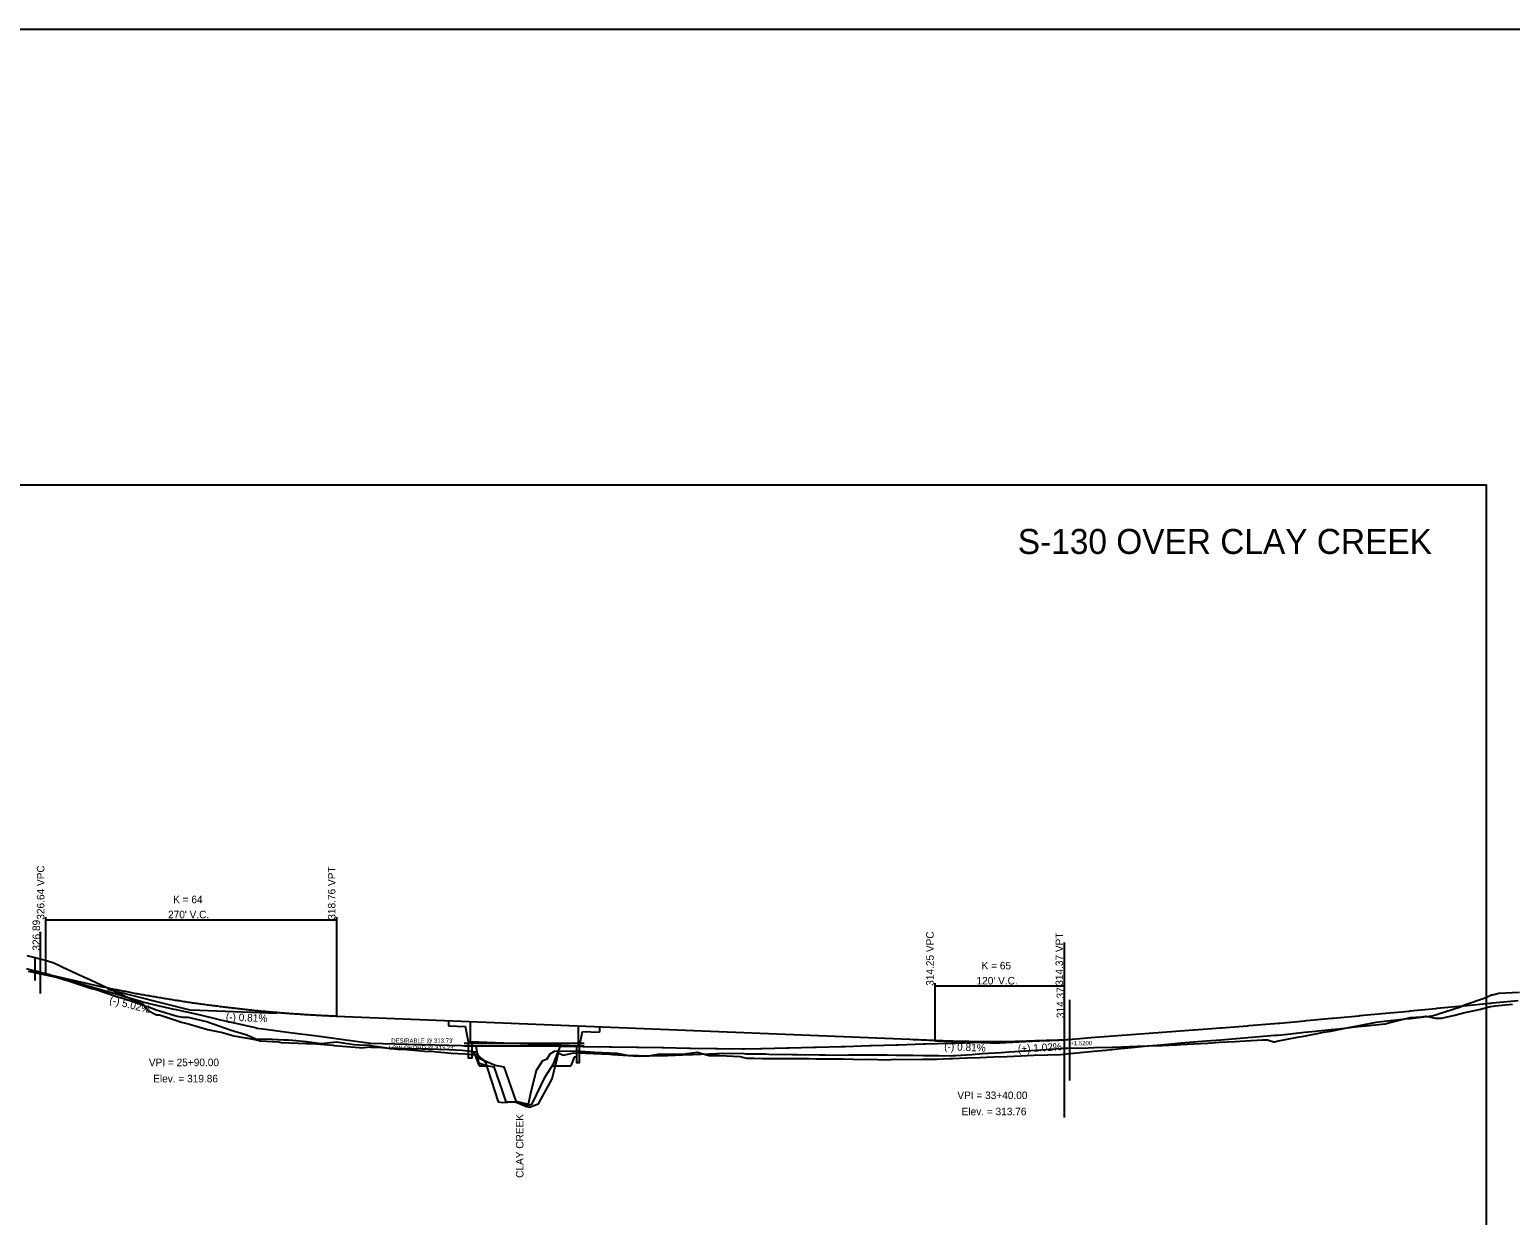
# Model space of a CAD drawing. Extents: x 2230305 to 2233905, y 1078764 to 1080964.
# Drawn here: x 2231649 to 2233023, y 1079864 to 1080964 of the extents above; entities that cross this region are included whole.
import ezdxf

# ---------------------------------------------------------------- set-up
doc = ezdxf.new("R2010")
doc.units = 0
for name, color, linetype in [('BR_CONCRETE', 7, 'Continuous'), ('BR_EXIST_GROUND_LT', 7, 'Continuous'), ('BR_EXIST_GROUND_RT', 7, 'Continuous'), ('BR_USER NOTES', 7, 'Continuous'), ('RD_DDB_GradeTX', 7, 'Continuous'), ('RD_DDB_Profile_EX', 7, 'Continuous'), ('RD_DDB_Profile_Lbl', 7, 'Continuous'), ('RD_DDB_Profile_PR', 7, 'Continuous'), ('RD_DDB_StripGrade', 7, 'Continuous'), ('RD_DDB_VCLbl', 7, 'Continuous'), ('RD_SHT_IplotShp', 7, 'Continuous'), ('RD_SHT_ShtClip', 7, 'Continuous'), ('RD_SHT_TX', 7, 'Continuous')]:
    doc.layers.add(name, color=color, linetype=linetype)

msp = doc.modelspace()

# ---------------------------------------------------------------- linework, layer by layer
at = {"layer": 'BR_CONCRETE'}
for p, q in [((2232038.2, 1080044.4), (2232038.2, 1080039.4)), ((2232038.2, 1080039.4), (2232053.9, 1080038.8)), ((2232056.7, 1080024.7), (2232053.9, 1080038.8)), ((2232058.2, 1080043.6), (2232058.2, 1080025.1)), ((2232158.2, 1080039.5), (2232158.2, 1080021)), ((2232178.2, 1080038.7), (2232178.2, 1080033.7)), ((2232058.2, 1080025.1), (2232158.2, 1080021)), ((2232058.2, 1080025.1), (2232058.2, 1080024.7)), ((2232159.7, 1080020.6), (2232162.4, 1080034.4)), ((2232162.4, 1080034.4), (2232178.2, 1080033.7)), ((2232059.7, 1080014.7), (2232061.7, 1080014.7)), ((2232061.7, 1080014.7), (2232066.6, 1080002.3)), ((2232154.7, 1080010.6), (2232151.4, 1080002.3)), ((2232156.7, 1080010.6), (2232154.7, 1080010.6)), ((2232158.2, 1080021), (2232158.2, 1080020.6)), ((2232066.6, 1080002.3), (2232074.8, 1080002.3)), ((2232134.2, 1080002.3), (2232151.4, 1080002.3))]:
    msp.add_line(p, q, dxfattribs=at)
for points in [[(2232056.7, 1080024.7), (2232059.7, 1080024.7), (2232059.7, 1080009.7), (2232056.7, 1080009.7)], [(2232159.7, 1080020.6), (2232156.7, 1080020.6), (2232156.7, 1080005.6), (2232159.7, 1080005.6)]]:
    msp.add_lwpolyline(points, close=True, dxfattribs=at)
at = {"layer": 'BR_EXIST_GROUND_LT'}
msp.add_lwpolyline([(2231647, 1080104.8), (2231665, 1080100.1), (2231672, 1080097.9), (2231677.9, 1080095.1), (2231680.4, 1080094), (2231697.7, 1080085.9), (2231705.3, 1080082.4), (2231721.7, 1080074.7), (2231730.2, 1080070.8), (2231745.4, 1080063.7), (2231755.2, 1080059.2), (2231758.7, 1080054.1), (2231767.3, 1080049.8), (2231768.6, 1080049.9), (2231769.9, 1080049.6), (2231790.3, 1080042.8), (2231797.9, 1080041.2), (2231814.6, 1080036), (2231828.5, 1080033.3), (2231839, 1080030.3), (2231858.8, 1080026.9), (2231863.4, 1080025.7), (2231864.1, 1080025.5), (2231880.5, 1080024.7), (2231882.8, 1080024.1), (2231906.4, 1080023.3), (2231906.8, 1080023.3), (2231911.7, 1080023.2), (2231930.9, 1080021.5), (2231931.9, 1080021.4), (2231955.1, 1080019.3), (2231957.2, 1080019), (2231965, 1080020.1), (2231965.7, 1080020), (2231966.3, 1080019.9), (2231973.5, 1080019.7), (2231990.8, 1080017.9), (2231999.3, 1080017.7), (2232015.7, 1080016), (2232024.9, 1080015.8), (2232040.6, 1080014.3), (2232053.5, 1080013.6), (2232064.4, 1080012.6), (2232066.2, 1080011.1), (2232070.3, 1080008.1), (2232072.3, 1080005.4), (2232074.7, 1079998.7), (2232084.2, 1079969.1), (2232088.3, 1079968.3), (2232097.9, 1079969.1), (2232101.7, 1079969.2), (2232112.3, 1079966.8), (2232114.1, 1079975.8), (2232119.8, 1079998.3), (2232125.7, 1080007.3), (2232129.5, 1080008.9), (2232132.5, 1080013.6), (2232136.5, 1080016.1), (2232156.6, 1080016.3), (2232173.8, 1080015), (2232194.1, 1080014.3), (2232205, 1080012.1), (2232214.4, 1080011.9), (2232223.3, 1080011.8), (2232234.5, 1080013.5), (2232254.7, 1080013.4), (2232268.6, 1080015.2), (2232279.9, 1080012.1), (2232289.4, 1080012), (2232289.8, 1080012), (2232308.3, 1080011.2), (2232314.5, 1080009.4), (2232321.3, 1080009.4), (2232329.4, 1080009.3), (2232344.2, 1080009.2), (2232354.3, 1080009.1), (2232372.4, 1080009.1), (2232379.2, 1080009), (2232399.8, 1080009), (2232404.2, 1080008.9), (2232422.1, 1080008.3), (2232428.1, 1080008.5), (2232444.5, 1080008.1), (2232453.1, 1080008.5), (2232467.6, 1080008.2), (2232478.1, 1080008.7), (2232490.9, 1080008.6), (2232503.1, 1080009.2), (2232504.5, 1080009.2), (2232505.9, 1080009.3), (2232518.7, 1080009.8), (2232530.9, 1080010.2), (2232543.8, 1080010.7), (2232555.9, 1080011.2), (2232568.9, 1080011.7), (2232580.9, 1080012.2), (2232594, 1080012.6), (2232605.9, 1080013.1), (2232608.8, 1080013.4), (2232611.8, 1080013.7), (2232624.1, 1080014.7), (2232636.8, 1080016), (2232647.9, 1080017), (2232661.9, 1080018.4), (2232671.7, 1080019.3), (2232686.9, 1080020.9), (2232695.5, 1080021.6), (2232712, 1080023.3), (2232717.3, 1080023.7), (2232729.6, 1080024.7), (2232737, 1080025.2), (2232754.6, 1080026.7), (2232761.8, 1080027.2), (2232779.6, 1080028.7), (2232786.6, 1080029.2), (2232804.6, 1080030.8), (2232805.4, 1080030.8), (2232807, 1080031), (2232813.9, 1080031.6), (2232832, 1080033.6), (2232838.9, 1080034.2), (2232857, 1080036.2), (2232864, 1080036.8), (2232882, 1080038.8), (2232889.1, 1080039.4), (2232906.9, 1080041.3), (2232910.4, 1080042.2), (2232916.6, 1080043.8), (2232930.2, 1080047.2), (2232940.4, 1080047.9), (2232942.6, 1080048.1), (2232944.8, 1080048.5), (2232953.8, 1080046.8), (2232954.8, 1080046.8), (2232959.2, 1080046.8), (2232971.6, 1080049.4), (2232979.8, 1080051.5), (2232994.1, 1080054.8), (2233004.8, 1080057.6), (2233007.1, 1080057.8), (2233009, 1080058.2), (2233025.2, 1080059.7)], dxfattribs=at)
at = {"layer": 'BR_EXIST_GROUND_RT'}
msp.add_lwpolyline([(2231648, 1080090.3), (2231651.1, 1080089.7), (2231673, 1080085.1), (2231674.4, 1080084.7), (2231682.1, 1080082.2), (2231686.4, 1080081.1), (2231707, 1080074.2), (2231711.2, 1080073.2), (2231731.9, 1080066.1), (2231736.1, 1080065.3), (2231756.9, 1080058), (2231757.5, 1080057.8), (2231761.5, 1080056.5), (2231766.8, 1080054.4), (2231786.4, 1080048.6), (2231791.5, 1080047.6), (2231796.7, 1080047.6), (2231797.8, 1080047.3), (2231799.1, 1080047), (2231814.9, 1080043.2), (2231815.5, 1080043.1), (2231836.4, 1080035.5), (2231850.9, 1080031.3), (2231859.8, 1080027.3), (2231860.5, 1080027.3), (2231868.9, 1080027.6), (2231885.2, 1080026.5), (2231889.7, 1080026.6), (2231906.4, 1080025), (2231910.2, 1080024.4), (2231910.9, 1080024.3), (2231920, 1080023.2), (2231934.2, 1080024.6), (2231950.5, 1080022.1), (2231955.5, 1080021.8), (2231965.1, 1080021.5), (2231965.7, 1080021.4), (2231980.9, 1080019.1), (2231991.2, 1080018.9), (2232002.8, 1080018.6), (2232013.4, 1080018.2), (2232018.9, 1080018.1), (2232038.4, 1080017.6), (2232050.6, 1080016.9), (2232063.8, 1080015.3), (2232067, 1080009.2), (2232081.3, 1080003), (2232089.3, 1080001.6), (2232097.9, 1079976.7), (2232100.7, 1079968.6), (2232110.4, 1079964.6), (2232113.3, 1079964.1), (2232119.8, 1079966.7), (2232121.7, 1079967.1), (2232134.1, 1079990.5), (2232139.3, 1080010.4), (2232140.1, 1080014.3), (2232140.7, 1080014.1), (2232144.3, 1080012.2), (2232154.4, 1080014.4), (2232164.7, 1080014.2), (2232179.9, 1080013.6), (2232184.9, 1080013.5), (2232190.4, 1080013.1), (2232209.6, 1080011.6), (2232215.4, 1080011.5), (2232233.4, 1080012.1), (2232237.1, 1080012.1), (2232241.3, 1080012.1), (2232262.1, 1080012.9), (2232264.6, 1080012.9), (2232287.1, 1080013.9), (2232287.6, 1080013.9), (2232292.6, 1080014.1), (2232312.1, 1080013.8), (2232313.8, 1080013.7), (2232332, 1080013.5), (2232335.2, 1080013.4), (2232356.9, 1080013.1), (2232361.4, 1080013), (2232381.8, 1080012.7), (2232387.7, 1080012.5), (2232406.7, 1080012.2), (2232409.8, 1080012.7), (2232425, 1080012.6), (2232428.7, 1080012.6), (2232445, 1080012.5), (2232453.7, 1080012.3), (2232468.8, 1080012.3), (2232478.8, 1080012.1), (2232492.7, 1080012), (2232503.9, 1080011.8), (2232506.4, 1080011.9), (2232508.4, 1080012.1), (2232523.6, 1080013.1), (2232533.2, 1080013.8), (2232550.9, 1080014.9), (2232558.1, 1080015.4), (2232578.3, 1080016.8), (2232583, 1080017.1), (2232605.8, 1080018.6), (2232607.8, 1080018.8), (2232611.8, 1080018.9), (2232612.3, 1080018.9), (2232631.5, 1080019.2), (2232637.4, 1080019.5), (2232654, 1080019.8), (2232662.4, 1080020.2), (2232676.9, 1080020.6), (2232687.5, 1080021), (2232700.1, 1080021.3), (2232712.6, 1080021.9), (2232713.6, 1080022), (2232717.4, 1080022.1), (2232729.2, 1080022.9), (2232742.6, 1080023.6), (2232753.4, 1080024.3), (2232767.9, 1080025.1), (2232777.5, 1080025.7), (2232793.2, 1080026.5), (2232797.8, 1080026.5), (2232803.7, 1080024.7), (2232804.5, 1080024.8), (2232806.5, 1080025.2), (2232825.7, 1080029.1), (2232831.5, 1080030), (2232850.1, 1080033.8), (2232856.5, 1080034.7), (2232874.4, 1080038.4), (2232881.4, 1080039.4), (2232898.5, 1080042.9), (2232906.4, 1080044), (2232925.8, 1080046.1), (2232930.5, 1080046.3), (2232950.4, 1080048.7), (2232954.8, 1080050), (2232955.5, 1080050.4), (2232976.9, 1080057.2), (2232980.6, 1080058.9), (2232999.7, 1080065.4), (2233005.6, 1080068.2), (2233006.6, 1080068.2), (2233012.4, 1080069.7), (2233031.5, 1080070.8)], dxfattribs=at)
at = {"layer": 'BR_USER NOTES'}
for p, q in [((2231659.2, 1080126.7), (2231659.2, 1080069.6)), ((2232609.2, 1080117), (2232609.2, 1079954.6)), ((2231654.2, 1080103.6), (2231654.2, 1080081.5)), ((2231659.2, 1080089.3), (2231654.2, 1080090.7)), ((2232614.2, 1080063.7), (2232614.2, 1079988.8)), ((2232609.2, 1080026.7), (2232614.2, 1080027.1)), ((2232052.7, 1080023.5), (2232164, 1080023.5)), ((2232052.7, 1080021), (2232164, 1080021))]:
    msp.add_line(p, q, dxfattribs=at)
at = {"layer": 'RD_DDB_GradeTX'}
for p, q in [((2231721.6, 1080073.6), (2231799.2, 1080054.1)), ((2231879.1, 1080050.9), (2231799.2, 1080054.1)), ((2232469.2, 1080026.9), (2232549.2, 1080023.6)), ((2232489.2, 1080025.5), (2232549.2, 1080023.6)), ((2232609.2, 1080026.7), (2232549.2, 1080023.6))]:
    msp.add_line(p, q, dxfattribs=at)
at = {"layer": 'RD_DDB_Profile_EX'}
msp.add_lwpolyline([(2231646.7, 1080092.7), (2231668.3, 1080086.7), (2231671.7, 1080085.8), (2231679.3, 1080083.6), (2231680.5, 1080083.3), (2231702.4, 1080076.9), (2231705.5, 1080076), (2231727.6, 1080069.7), (2231730.4, 1080068.8), (2231752.8, 1080062.4), (2231755.4, 1080061.6), (2231759.8, 1080060.6), (2231760.3, 1080060.4), (2231783.4, 1080055.1), (2231785.3, 1080054.7), (2231808.9, 1080049.3), (2231810.2, 1080049), (2231834.3, 1080043.4), (2231835.2, 1080043.2), (2231859.8, 1080037.6), (2231860.1, 1080037.5), (2231865.8, 1080036.7), (2231866.1, 1080036.7), (2231891, 1080033.4), (2231915.9, 1080030.2), (2231940.8, 1080026.9), (2231965.7, 1080023.6), (2231988.5, 1080023), (2232012.8, 1080022.3), (2232013.5, 1080022.3), (2232037.5, 1080021.6), (2232038.5, 1080021.6), (2232062.1, 1080020.9), (2232063.5, 1080020.9), (2232065.9, 1080005.1), (2232073.3, 1080002.6), (2232080.2, 1080001.4), (2232087.9, 1079979.1), (2232091.4, 1079969.1), (2232100, 1079969.1), (2232104.1, 1079967.4), (2232112.5, 1079965.9), (2232115.6, 1079967.2), (2232127.8, 1079992.3), (2232135.4, 1080004.2), (2232141.8, 1080020.2), (2232142.2, 1080020.7), (2232162.7, 1080020.4), (2232164.2, 1080020.4), (2232187.5, 1080020.1), (2232189.2, 1080020), (2232212.4, 1080019.7), (2232214.2, 1080019.7), (2232236.1, 1080019.3), (2232237.7, 1080019.3), (2232260.9, 1080018.9), (2232262.7, 1080018.9), (2232285.8, 1080018.5), (2232287.7, 1080018.5), (2232310.7, 1080018.1), (2232312.7, 1080018.1), (2232327.7, 1080018.5), (2232329.1, 1080018.5), (2232352, 1080019.1), (2232354.1, 1080019.2), (2232377.1, 1080019.8), (2232379.1, 1080019.8), (2232402.2, 1080020.4), (2232404.1, 1080020.5), (2232405.9, 1080020.5), (2232428.8, 1080021.2), (2232430.6, 1080021.3), (2232453.8, 1080022), (2232455.4, 1080022), (2232478.8, 1080022.7), (2232480.3, 1080022.8), (2232504, 1080023.5), (2232507.3, 1080023.6), (2232508.6, 1080023.6), (2232532.3, 1080024.3), (2232533.2, 1080024.4), (2232557.3, 1080025.1), (2232557.9, 1080025.1), (2232582.5, 1080025.8), (2232592.6, 1080026.1), (2232607.4, 1080026.5), (2232613, 1080027), (2232638, 1080028.9), (2232663, 1080030.8), (2232688, 1080032.7), (2232712.9, 1080034.6), (2232729.2, 1080035.8), (2232729.8, 1080035.9), (2232754.2, 1080037.7), (2232755.2, 1080037.8), (2232779.2, 1080039.6), (2232780.6, 1080039.8), (2232804.2, 1080041.6), (2232804.5, 1080041.6), (2232807.6, 1080041.9), (2232809.4, 1080042.1), (2232832.6, 1080044.2), (2232834.1, 1080044.4), (2232857.6, 1080046.6), (2232858.8, 1080046.7), (2232882.5, 1080048.9), (2232883.5, 1080049), (2232907.5, 1080051.2), (2232929.2, 1080053.3), (2232930, 1080053.4), (2232954, 1080055.7), (2232955, 1080055.8), (2232978.8, 1080058.1), (2232979.9, 1080058.2), (2233003.7, 1080060.5), (2233004.9, 1080060.6), (2233006.6, 1080060.8), (2233030.3, 1080063)], dxfattribs=at)
at = {"layer": 'RD_DDB_Profile_PR'}
for p, q in [((2231659.2, 1080089.3), (2231664.2, 1080088)), ((2231934.2, 1080048.6), (2232489.2, 1080026.1))]:
    msp.add_line(p, q, dxfattribs=at)
for points in [[(2231664.2, 1080088), (2231669.6, 1080086.7), (2231675, 1080085.4), (2231680.4, 1080084.1), (2231685.8, 1080082.8), (2231691.2, 1080081.5), (2231696.6, 1080080.3), (2231702, 1080079.1), (2231707.4, 1080077.9), (2231712.8, 1080076.7), (2231718.2, 1080075.6), (2231723.6, 1080074.5), (2231729, 1080073.4), (2231734.4, 1080072.3), (2231739.8, 1080071.3), (2231745.2, 1080070.2), (2231750.6, 1080069.2), (2231756, 1080068.3), (2231761.4, 1080067.3), (2231766.8, 1080066.4), (2231772.2, 1080065.5), (2231777.6, 1080064.6), (2231783, 1080063.7), (2231788.4, 1080062.9), (2231793.8, 1080062), (2231799.2, 1080061.2), (2231804.6, 1080060.5), (2231810, 1080059.7), (2231815.4, 1080059), (2231820.8, 1080058.3), (2231826.2, 1080057.6), (2231831.6, 1080056.9), (2231837, 1080056.3), (2231842.4, 1080055.7), (2231847.8, 1080055.1), (2231853.2, 1080054.5), (2231858.6, 1080053.9), (2231864, 1080053.4), (2231869.4, 1080052.9), (2231874.8, 1080052.4), (2231880.2, 1080052), (2231885.6, 1080051.5), (2231891, 1080051.1), (2231896.4, 1080050.7), (2231901.8, 1080050.4), (2231907.2, 1080050), (2231912.6, 1080049.7), (2231918, 1080049.4), (2231923.4, 1080049.1), (2231928.8, 1080048.9), (2231934.2, 1080048.6)], [(2232489.2, 1080026.1), (2232491.6, 1080026), (2232494, 1080025.9), (2232496.4, 1080025.8), (2232498.8, 1080025.7), (2232501.2, 1080025.6), (2232503.6, 1080025.6), (2232506, 1080025.5), (2232508.4, 1080025.4), (2232510.8, 1080025.4), (2232513.2, 1080025.3), (2232515.6, 1080025.3), (2232518, 1080025.2), (2232520.4, 1080025.2), (2232522.8, 1080025.1), (2232525.2, 1080025.1), (2232527.6, 1080025.1), (2232530, 1080025), (2232532.4, 1080025), (2232534.8, 1080025), (2232537.2, 1080025), (2232539.6, 1080025), (2232542, 1080025), (2232544.4, 1080025), (2232546.8, 1080025), (2232549.2, 1080025), (2232551.6, 1080025), (2232554, 1080025), (2232556.4, 1080025.1), (2232558.8, 1080025.1), (2232561.2, 1080025.1), (2232563.6, 1080025.2), (2232566, 1080025.2), (2232568.4, 1080025.2), (2232570.8, 1080025.3), (2232573.2, 1080025.3), (2232575.6, 1080025.4), (2232578, 1080025.5), (2232580.4, 1080025.5), (2232582.8, 1080025.6), (2232585.2, 1080025.7), (2232587.6, 1080025.8), (2232590, 1080025.8), (2232592.4, 1080025.9), (2232594.8, 1080026), (2232597.2, 1080026.1), (2232599.6, 1080026.2), (2232602, 1080026.3), (2232604.4, 1080026.4), (2232606.8, 1080026.6), (2232609.2, 1080026.7)]]:
    msp.add_spline(points, degree=3, dxfattribs=at)
at = {"layer": 'RD_DDB_VCLbl'}
for p, q in [((2231664.2, 1080140.5), (2231664.2, 1080088)), ((2231664.2, 1080138), (2231934.2, 1080138)), ((2231934.2, 1080140.5), (2231934.2, 1080048.6)), ((2232489.2, 1080079.2), (2232489.2, 1080026.1)), ((2232609.2, 1080079.2), (2232609.2, 1080026.7)), ((2232489.2, 1080076.7), (2232609.2, 1080076.7))]:
    msp.add_line(p, q, dxfattribs=at)
at = {"layer": 'RD_SHT_IplotShp'}
msp.add_lwpolyline([(2230304.7, 1078763.7), (2233904.7, 1078763.7), (2233904.7, 1080963.7), (2230304.7, 1080963.7)], close=True, dxfattribs=at)
at = {"layer": 'RD_SHT_ShtClip'}
msp.add_lwpolyline([(2233000.6, 1079441.3), (2231200.6, 1079441.3), (2231200.6, 1080541.3), (2233000.6, 1080541.3)], close=True, dxfattribs=at)

# ---------------------------------------------------------------- texts
at = {"layer": 'BR_USER NOTES'}
for s, p in [('326.89', (2231659.2, 1080109.3)), ('314.37', (2232609.2, 1080046.7))]:
    msp.add_text(s, height=7, rotation=90, dxfattribs=at).set_placement(p)
for s, p in [("DESIRABLE @ 313.73'", (2231985, 1080023.8)), ('+1.5200', (2232615, 1080021.5)), ("LOW CHORD @ 313.23'", (2231982.7, 1080017.3))]:
    msp.add_text(s, height=4, dxfattribs=at).set_placement(p)
at = {"layer": 'RD_DDB_GradeTX'}
for s, rotation, p in [('(-) 5.02%', 345.9098, (2231723, 1080060.5)), ('(-) 0.81%', 357.6703, (2231831.4, 1080044.5)), ('(-) 0.81%', 357.6703, (2232497.8, 1080017.1)), ('(+) 1.02%', 2.9196, (2232566.4, 1080014.8))]:
    msp.add_text(s, height=7, rotation=rotation, dxfattribs=at).set_placement(p)
at = {"layer": 'RD_DDB_Profile_Lbl'}
for s, p in [('VPI = 25+90.00', (2231760.1, 1080002.1)), ('Elev. = 319.86', (2231764.1, 1079987.1)), ('VPI = 33+40.00', (2232510.1, 1079971.6)), ('Elev. = 313.76', (2232514.1, 1079956.6))]:
    msp.add_text(s, height=7, dxfattribs=at).set_placement(p)
msp.add_text('CLAY CREEK', height=7, rotation=90, dxfattribs=at).set_placement((2232107.6, 1079898.5))
at = {"layer": 'RD_DDB_StripGrade'}
for s, p in [('326.64 VPC', (2231663.2, 1080138)), ('318.76 VPT', (2231933.2, 1080138)), ('314.25 VPC', (2232488.2, 1080076.7)), ('314.37 VPT', (2232608.2, 1080076.7))]:
    msp.add_text(s, height=7, rotation=90, dxfattribs=at).set_placement(p)
at = {"layer": 'RD_DDB_VCLbl'}
for s, p in [('K = 64', (2231782.6, 1080153.3)), ("270' V.C.", (2231777.9, 1080139.3)), ('K = 65', (2232532.6, 1080091.9)), ("120' V.C.", (2232527.9, 1080077.9))]:
    msp.add_text(s, height=7, dxfattribs=at).set_placement(p)
at = {"layer": 'RD_SHT_TX'}
msp.add_text('S-130 OVER CLAY CREEK', height=23.182, rotation=360, dxfattribs=at).set_placement((2232566.2, 1080477.3))

doc.saveas('drawing.dxf')
